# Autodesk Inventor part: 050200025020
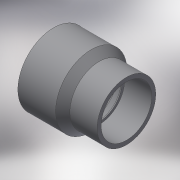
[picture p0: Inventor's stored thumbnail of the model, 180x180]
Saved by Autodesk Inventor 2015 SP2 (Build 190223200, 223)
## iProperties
Created: 2017-10
Part Number: 050200025020
Material: Generic
Description: PLASSON REDUCING SOCKET M.F.25(20)20 CEMENTED
Document SubType Name: Modeling
Designer: KIM
Density: 1 g/cm^3
Appearance: Default
Author: KIM
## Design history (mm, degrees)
derived "050200.ipt"
feature "Solid1::050200.ipt"
tag "TaggingFeature1"
body "Solid1"
other parameters: "d0" = 42, "d1" = 19, "d2" = 16, "d3" = 16, "d5" = 25, "d7" = 25, "d8" = 18, "d9" = 45 deg, "d12" = 0.2, "L_" = 19, "l_" = 16, "l_1" = 16, "E_" = 25, "H_" = 42, "D_" = 25, "d11" = 0
